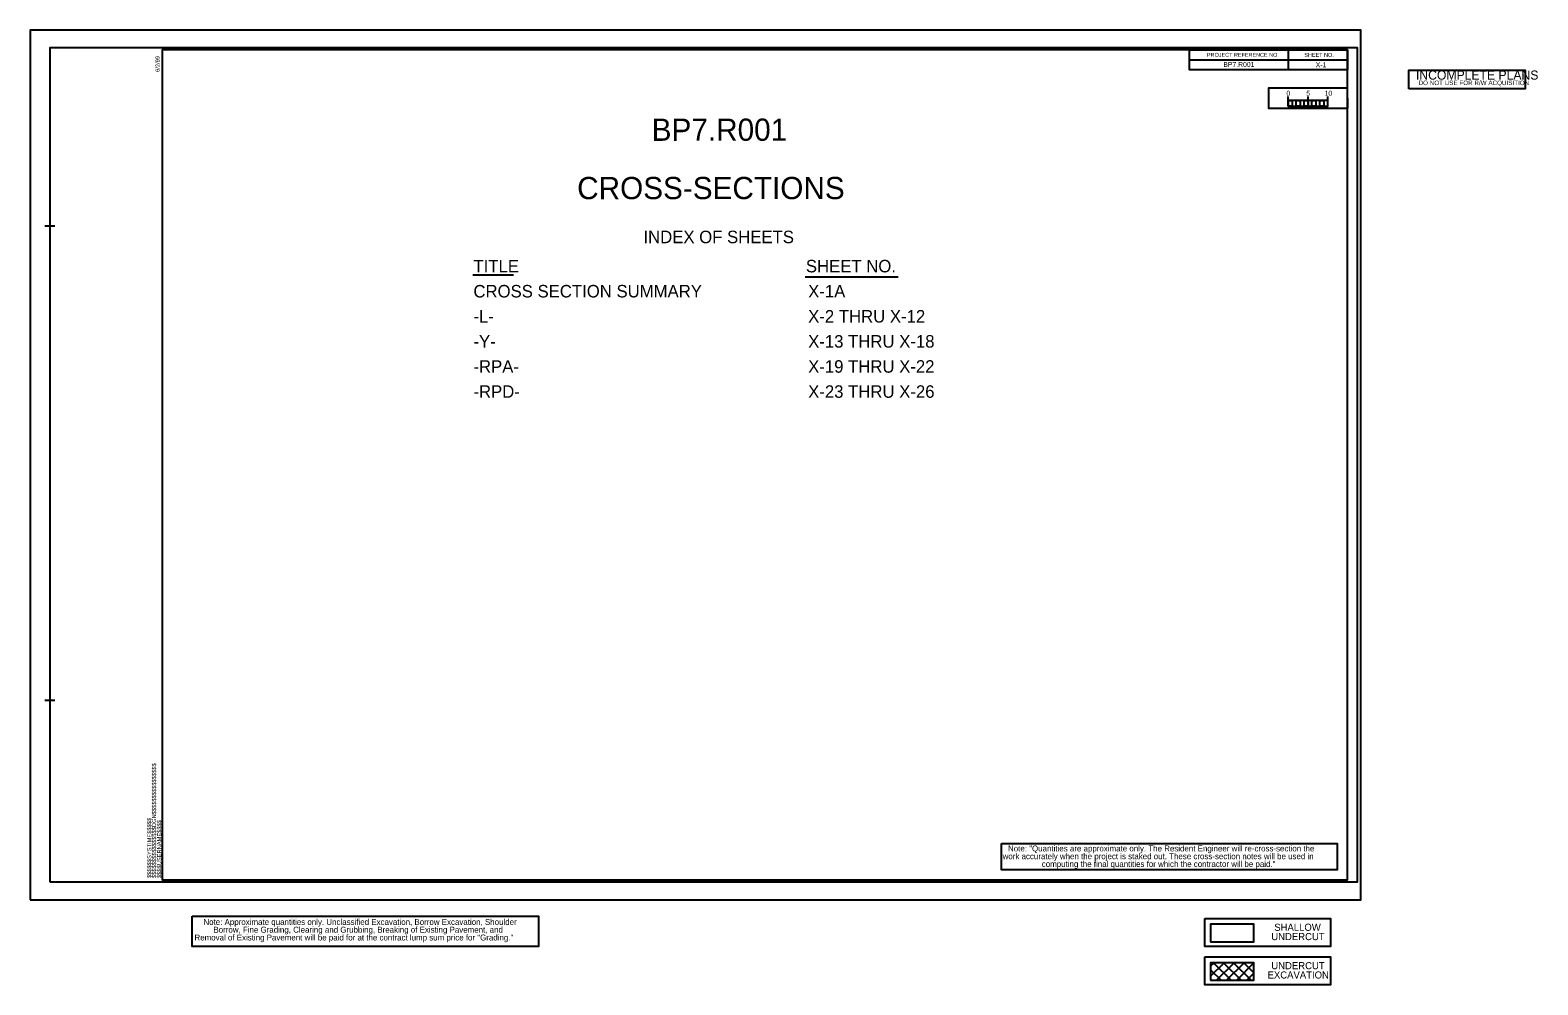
# Model space of a CAD drawing. Extents: x -19 to 363, y -22 to 220.
import ezdxf

# ---------------------------------------------------------------- set-up
doc = ezdxf.new("R2010")
doc.units = 0
for name, color, linetype in [('Old_Level_2', 7, 'Continuous'), ('Old_Level_38', 7, 'Continuous'), ('Old_Level_40', 7, 'Continuous'), ('Old_Level_41', 7, 'Continuous'), ('Old_Level_44', 7, 'Continuous'), ('Old_Level_62', 7, 'Continuous'), ('Old_Level_63', 7, 'Continuous'), ('Prop Grid Mask', 7, 'Continuous'), ('Prop Shade Light', 7, 'Continuous'), ('Prop XS Undercut Exc Hatch', 7, 'Continuous'), ('Prop XSC Text', 7, 'Continuous'), ('Sheet Sticker Incomplete CELL', 7, 'Continuous'), ('Sheet Summary Combination CELL', 7, 'Continuous'), ('Sheet Typical CELL', 7, 'Continuous')]:
    doc.layers.add(name, color=color, linetype=linetype)

msp = doc.modelspace()

# ---------------------------------------------------------------- linework, layer by layer
at = {"layer": 'Old_Level_2'}
for points in [[(278.31, -4.75), (310.09, -4.75), (310.09, -11.83), (278.31, -11.83)], [(279.77, -10.66), (290.76, -10.66), (290.76, -6.22), (279.77, -6.22)]]:
    msp.add_lwpolyline(points, close=True, dxfattribs=at)
at = {"layer": 'Old_Level_38'}
for p, q in [((299.45, 200.79), (299.45, 203.2)), ((299.45, 202.2), (299.45, 203.2)), ((304.45, 200.79), (304.45, 203.2)), ((309.45, 200.79), (309.45, 203.2)), ((309.45, 202.2), (309.45, 203.2))]:
    msp.add_line(p, q, dxfattribs=at)
for points in [[(309.45, 202.2), (299.45, 202.2), (299.45, 200.79), (309.45, 200.79)], [(299.45, 202.2), (300.45, 202.2), (300.45, 200.79), (299.45, 200.79)], [(301.45, 202.2), (302.45, 202.2), (302.45, 200.79), (301.45, 200.79)], [(303.45, 202.2), (304.45, 202.2), (304.45, 200.79), (303.45, 200.79)], [(305.45, 202.2), (306.45, 202.2), (306.45, 200.79), (305.45, 200.79)], [(307.45, 202.2), (308.45, 202.2), (308.45, 200.79), (307.45, 200.79)]]:
    msp.add_lwpolyline(points, close=True, dxfattribs=at)
at = {"layer": 'Old_Level_40'}
msp.add_line((314.45, 202.8), (314.45, 200.3), dxfattribs=at)
msp.add_lwpolyline([(314.45, 205.3), (294.45, 205.3), (294.45, 200.3), (314.45, 200.3)], close=True, dxfattribs=at)
at = {"layer": 'Old_Level_41'}
msp.add_line((294.45, 205.3), (294.45, 200.33), dxfattribs=at)
at = {"layer": 'Old_Level_62'}
msp.add_lwpolyline([(-14, 4.5), (316.95, 4.5), (316.95, 215.52), (-14, 215.52)], close=True, dxfattribs=at)
at = {"layer": 'Old_Level_63'}
msp.add_lwpolyline([(-18.95, 0.01), (317.85, 0.01), (317.85, 220.01), (-18.95, 220.01)], close=True, dxfattribs=at)
at = {"layer": 'Prop Grid Mask'}
for points in [[(226.89, 14.25), (311.84, 14.25), (311.84, 7.56), (226.89, 7.56)], [(22.04, -4.14), (109.72, -4.14), (109.72, -11.82), (22.04, -11.82)], [(278.31, -14.46), (310.09, -14.46), (310.09, -21.54), (278.31, -21.54)], [(279.77, -20.37), (290.76, -20.37), (290.76, -15.93), (279.77, -15.93)]]:
    msp.add_lwpolyline(points, close=True, dxfattribs=at)
at = {"layer": 'Prop Shade Light'}
for p, q in [((279.77, -10.56), (279.88, -10.66)), ((279.88, -10.66), (290.76, -10.66))]:
    msp.add_line(p, q, dxfattribs=at)
msp.add_lwpolyline([(290.76, -10.66), (290.76, -6.22), (279.77, -6.22), (279.77, -10.56)], dxfattribs=at)
at = {"layer": 'Prop XS Undercut Exc Hatch'}
for p, q in [((279.77, -10.56), (279.88, -10.66)), ((279.77, -16.81), (280.66, -15.93)), ((279.77, -19.36), (283.2, -15.93)), ((279.77, -17.72), (282.43, -20.37)), ((280.53, -15.93), (284.97, -20.37)), ((281.31, -20.37), (285.75, -15.93)), ((283.08, -15.93), (287.52, -20.37)), ((283.85, -20.37), (288.29, -15.93)), ((285.62, -15.93), (290.06, -20.37)), ((286.4, -20.37), (290.76, -16.01)), ((288.17, -15.93), (290.76, -18.52)), ((288.94, -20.37), (290.76, -18.56)), ((290.71, -15.93), (290.76, -15.97)), ((279.77, -20.26), (279.88, -20.37))]:
    msp.add_line(p, q, dxfattribs=at)
at = {"layer": 'Sheet Sticker Incomplete CELL'}
msp.add_lwpolyline([(329.97, 205.16), (329.97, 209.86), (359.37, 209.86), (359.37, 205.16)], close=True, dxfattribs=at)
at = {"layer": 'Sheet Summary Combination CELL'}
for p, q in [((93.08, 158.09), (103.37, 158.09)), ((177.16, 157.57), (200.73, 157.57))]:
    msp.add_line(p, q, dxfattribs=at)
at = {"layer": 'Sheet Typical CELL'}
for p, q in [((299.45, 215), (299.45, 210)), ((274.44, 212.5), (314.45, 212.5)), ((-15.25, 170.51), (-12.75, 170.51)), ((-15.25, 50.51), (-12.75, 50.51)), ((14.45, 5.01), (14.45, 5.01)), ((14.45, 5.01), (14.45, 5.01)), ((14.45, 5.01), (14.45, 5.01)), ((14.45, 5.01), (14.45, 5.01)), ((14.45, 5.01), (14.45, 5.01)), ((14.45, 5.01), (14.45, 5.01))]:
    msp.add_line(p, q, dxfattribs=at)
for points in [[(314.45, 215.01), (14.45, 215.01), (14.45, 5.01), (314.45, 5.01)], [(274.44, 215.01), (314.45, 215.01), (314.45, 210), (274.44, 210)]]:
    msp.add_lwpolyline(points, close=True, dxfattribs=at)

# ---------------------------------------------------------------- texts
at = {"layer": 'Old_Level_38'}
for s, p in [('0', (298.99, 203.42)), ('5', (304.01, 203.42)), ('10', (308.64, 203.42))]:
    msp.add_text(s, height=1.25, dxfattribs=at).set_placement(p)
at = {"layer": 'Old_Level_44'}
for s, p in [('BP7.R001', (283.01, 210.71)), ('X-1', (306.39, 210.63))]:
    msp.add_text(s, height=1.25, rotation=360, dxfattribs=at).set_placement(p)
at = {"layer": 'Prop XSC Text'}
for s, height, p in [('work accurately when the project is staked out. These cross-section notes will be used in', 1.5, (227.16, 10.25)), ('Note: "Quantities are approximate only. The Resident Engineer will re-cross-section the', 1.5, (228.53, 12.22)), ('computing the final quantities for which the contractor will be paid."', 1.5, (237.07, 8.29)), ('Note: Approximate quantities only. Unclassified Excavation, Borrow Excavation, Shoulder', 1.5, (24.9, -6.38)), ('Borrow, Fine Grading, Clearing and Grubbing, Breaking of Existing Pavement, and', 1.5, (27.43, -8.34)), ('SHALLOW', 1.8, (295.9, -7.87)), ('Removal of Existing Pavement will be paid for at the contract lump sum price for "Grading."', 1.5, (22.63, -10.31)), ('UNDERCUT', 1.8, (295.14, -10.23)), ('EXCAVATION', 1.8, (294.21, -19.94)), ('UNDERCUT', 1.8, (295.15, -17.58))]:
    msp.add_text(s, height=height, dxfattribs=at).set_placement(p)
at = {"layer": 'Sheet Sticker Incomplete CELL'}
for s, height, p in [('INCOMPLETE PLANS', 2.304, (331.76, 207.5)), ('DO NOT USE FOR R/W ACQUISITION', 1.152, (332.41, 206.11))]:
    msp.add_text(s, height=height, dxfattribs=at).set_placement(p)
at = {"layer": 'Sheet Summary Combination CELL'}
for s, height, p in [('BP7.R001', 5.625, (138.35, 192.01)), ('CROSS-SECTIONS', 5.625, (119.48, 177.25)), ('INDEX OF SHEETS', 3.1641, (136.26, 166.11)), ('TITLE', 3.164, (93.23, 158.73)), ('SHEET NO.', 3.164, (177.36, 158.73)), ('CROSS SECTION SUMMARY', 3.1641, (93.23, 152.38)), ('X-1A', 3.164, (177.94, 152.38)), ('-L- ', 3.164, (93.23, 146.03)), ('X-2 THRU X-12', 3.1641, (177.94, 146.03)), ('-Y-', 3.164, (93.23, 139.69)), ('X-13 THRU X-18', 3.1641, (177.94, 139.69)), ('-RPA-', 3.164, (93.23, 133.34)), ('X-19 THRU X-22', 3.1641, (177.94, 133.34)), ('-RPD-', 3.164, (93.23, 126.99)), ('X-23 THRU X-26', 3.1641, (177.94, 126.99))]:
    msp.add_text(s, height=height, rotation=0.0119, dxfattribs=at).set_placement(p)
at = {"layer": 'Sheet Typical CELL'}
for s, p in [('PROJECT REFERENCE NO.', (278.88, 213.27)), ('SHEET NO.', (303.51, 213.25))]:
    msp.add_text(s, height=1, dxfattribs=at).set_placement(p)
for s, p in [('6/2/99', (13.82, 209.46)), ('$$$$$$$$$$$$$$$$DGN$$$$$$$$$$$$$$$$', (12.92, 5.49)), ('$$$$$$SYSTIME$$$$$', (11.71, 5.49)), ('$$$$USERNAME$$$$', (14.23, 5.49))]:
    msp.add_text(s, height=1.05, rotation=90, dxfattribs=at).set_placement(p)

doc.saveas('drawing.dxf')
